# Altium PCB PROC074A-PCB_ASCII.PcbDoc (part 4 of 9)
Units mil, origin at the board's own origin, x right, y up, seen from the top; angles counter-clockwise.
Board outline 2755.91 x 5300 mil, 10 copper layers (Top Layer, L2-GND, L3-SIG1, L4-GND, L5-PWR/SIG, L6-SIG2, L7-PWR2, L8-SIG3, L9-GND, Bottom Layer), stack 67.57 mil thick; 586 components, 490 nets, 2137 pads, 1150 vias.
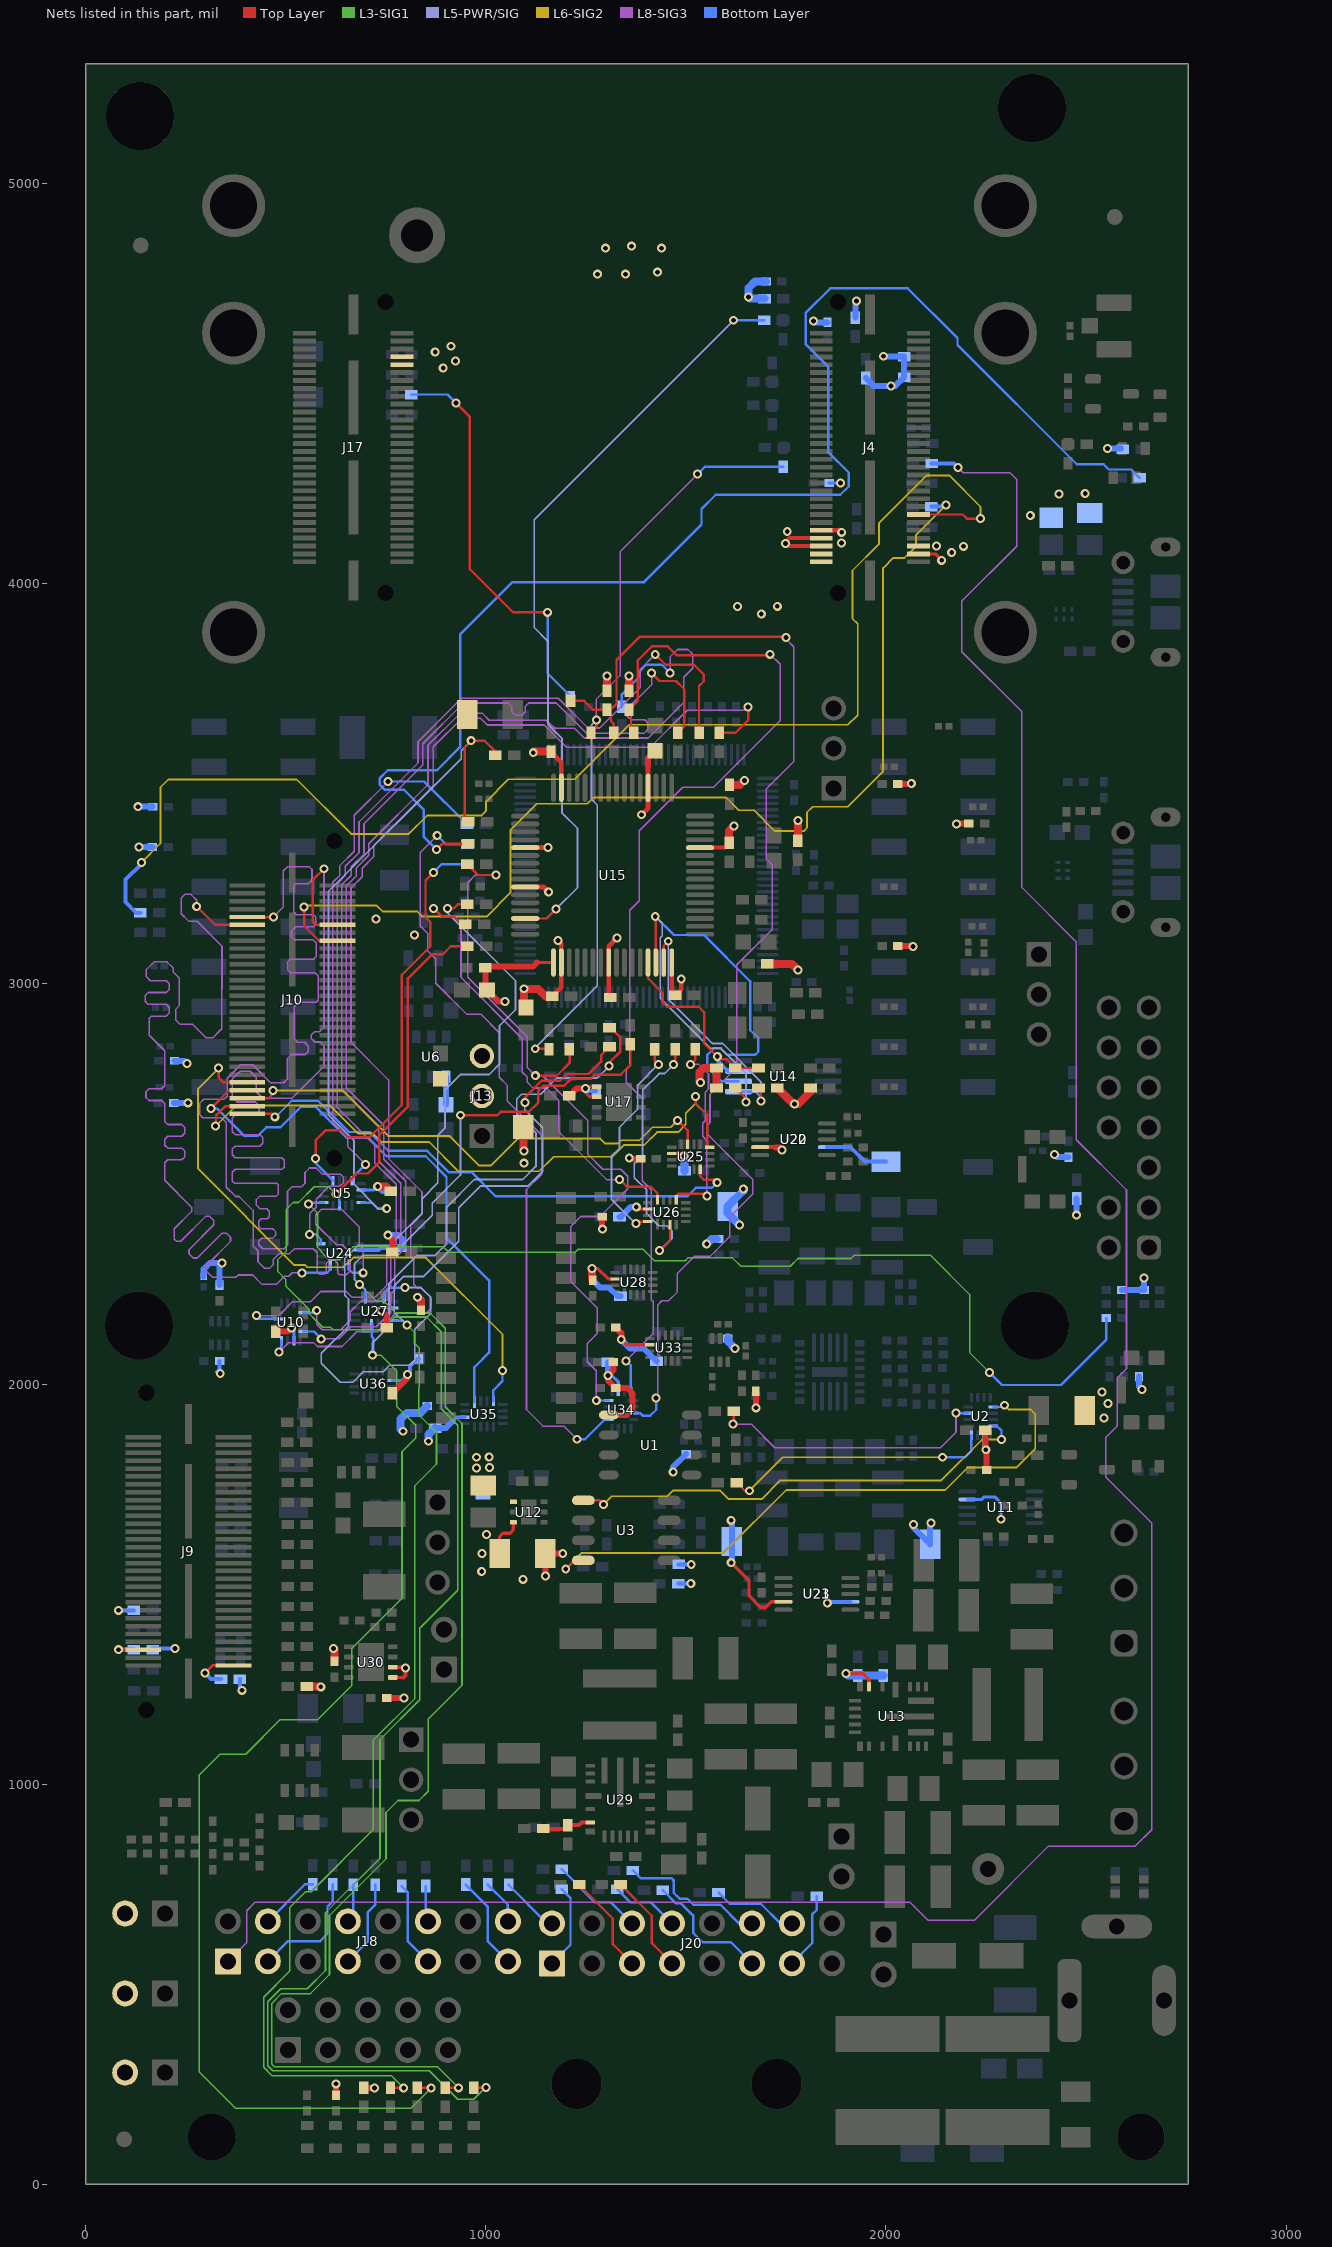
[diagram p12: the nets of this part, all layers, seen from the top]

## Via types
v1: diameter 22.4, hole 12.2, Top Layer to Bottom Layer, tented both sides, 1123 vias
v2: diameter 15.75, hole 7.87, Top Layer to Bottom Layer, tented both sides, 14 vias
v3: diameter 19.68, hole 7.87, Top Layer to Bottom Layer, tented both sides, 13 vias

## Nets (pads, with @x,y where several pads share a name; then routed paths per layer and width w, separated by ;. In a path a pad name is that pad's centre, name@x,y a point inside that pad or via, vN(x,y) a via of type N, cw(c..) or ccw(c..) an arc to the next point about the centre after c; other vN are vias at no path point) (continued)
60PIN_MISO1: J10.12 U24.8 | length 2879.4
  Top Layer w6: v1(595.37,3288.06) 567,3259.69 567,3156 575.41,3147.59 J10.12@629.09,3147.59
  L8-SIG3 w4: v1(559.37,2374.06) 559.37,2425.59 575.83,2442.05 575.83,2462.06 607.99,2494.22 635.22,2494.22 643,2502 643,2518 637,2524 592,2524 576,2540 559,2540 548,2529 548,2502 539.15,2493.15 515.31,2493.15 504.06,2481.9 504.06,2346.75 495.37,2338.06 442.31,2338.06 432.37,2348 432.37,2358.06 438.37,2364.06 466.37,2364.06 474.37,2372.06 474.37,2381.06 467.37,2388.06 437.37,2388.06 432.37,2393.06 432.37,2407.06 438.37,2413.06 453.46,2413.06 458.37,2417.97 458.37,2432.06 452.37,2438.06 435.37,2438.06 426.5,2446.92 426.5,2461.56 434,2469.06 475.37,2469.06 481.37,2475.06 481.37,2498.06 477.5,2501.93 371.5,2501.93 366.37,2507.06 366.37,2529.31 373.62,2536.56 490.56,2536.56 496,2542 496,2559.1 489.54,2565.56 373.62,2565.56 366.37,2572.81 366.37,2587.31 373.62,2594.56 434.92,2594.56 442.17,2601.81 442.17,2616.31 434.92,2623.56 373.62,2623.56 366.37,2630.81 366.37,2665 376.37,2675 425,2675 434,2684 434,2695 424,2705 378,2705 366.37,2716.63 366.37,2762.37 386.06,2782.06 410.96,2782.06 425.99,2767.03 425.99,2730.5 442.1,2714.39 515.56,2714.39 595.37,2794.21 595.37,2847 587.37,2855 572,2855 564,2863 564,2873 572,2881 585,2881 595.37,2891.37 v1(595.37,3288.06)
  Bottom Layer w6: v1(559.37,2374.06) 575.37,2374.06 587.39,2362.04 U24.8@587.39,2350.57
60PIN_MOSI1: J10.11 U24.4 | length 2967.3
  Top Layer w6: v1(277.22,3193.93) 323.55,3147.59 J10.11@403.5,3147.59
  L8-SIG3 w4: v1(277.22,3193.93) 277.22,3209.58 263,3223.8 247.4,3223.8 238.6,3215 238.6,3175.5 256.82,3157.28 277.22,3157.28 340.5,3094 340.5,2986.34 339.79,2985.63 339.79,2887.86 317.12,2865.2 301.22,2865.2 293,2873.41 ; 292.82,2873.24 267.12,2898.94 235.73,2898.94 224.33,2910.34 224.33,2936.44 233.95,2946.06 233.95,3014.48 218.98,3029.45 218.98,3039.06 202.84,3055.2 170.51,3055.2 151.57,3036.26 151.57,3018.12 161.39,3008.31 200.99,3008.31 208.37,3000.93 208.37,2986.18 200.99,2978.81 155.62,2978.81 148.25,2971.43 148.25,2956.68 155.62,2949.31 200.99,2949.31 208.37,2941.93 208.37,2927.18 200.99,2919.81 164.12,2919.81 158.37,2914.06 158.37,2872.01 197.37,2833.01 197.37,2745.68 189.99,2738.31 157.95,2738.31 150.58,2730.93 150.58,2716.18 157.95,2708.81 189.99,2708.81 197.37,2701.43 197.37,2656.18 204.74,2648.81 239.99,2648.81 247.37,2641.43 247.37,2626.68 239.99,2619.31 204.74,2619.31 197.37,2611.93 197.37,2597.18 204.74,2589.81 239.99,2589.81 247.37,2582.43 247.37,2567.68 239.99,2560.31 204.74,2560.31 197.37,2552.93 197.37,2509.06 264.37,2442.06 264.37,2431.06 221.37,2388.06 221.37,2362.06 226.58,2356.84 237.01,2356.84 299.19,2419.01 309.62,2419.01 320.05,2408.58 320.05,2398.15 257.87,2335.98 257.87,2325.55 268.3,2315.12 278.73,2315.12 340.91,2377.29 351.34,2377.29 361.76,2366.86 361.76,2356.43 299.59,2294.26 299.59,2283.83 316.82,2266.61 375.11,2266.61 381.01,2272.51 417,2272.51 440.45,2249.06 476.06,2249.06 496.61,2269.61 507.43,2269.61 515.82,2278 v1(540,2278)
  Bottom Layer w6: v1(540,2278) 603.4,2278 611.01,2285.61 U24.4@611.01,2295.45
60PIN_NRST: J10.59 U25.4 | length 1373.4
  Top Layer w6: J10.59@403.5,2675.15 465.27,2675.15 v1(472.37,2668.06) ; U25.4@1535.68,2536.88 1535.68,2519.75 1544.43,2511 1571.21,2511 v1(1578.26,2503.95)
  Bottom Layer w6: v1@473.44,2666.8 514.57,2707.92 580.13,2707.92 658.06,2630 709.2,2630 755.95,2583.25 853.11,2583.25 906.73,2529.63 963.85,2529.63 1024.48,2469 1503.4,2469 1524.66,2490.26 1564.57,2490.26 v1(1578.26,2503.95)
60PIN_PGOOD_3V3: J4.14 R224.2 | length 3351.6
  Top Layer w6: J4.14@2081.5,4173.45 2191.98,4173.45 2202.37,4163.06 v1(2236.37,4163.06)
  L6-SIG2 w4.5: v1(139.37,3304.06) 186.48,3351.17 186.48,3491.17 206.37,3511.06 526.94,3511.06 663,3375 807,3375 852.86,3420.86 988.74,3420.86 1000.57,3432.69 1000.57,3455.79 1056.33,3511.56 1221.87,3511.56 1358.11,3647.8 1904.99,3647.8 1929.37,3672.18 1929.37,3900.11 1916.43,3913.06 1916.43,4033.47 1982.37,4099.41 1982.37,4151.52 2102.08,4271.23 2157.97,4271.23 2236.37,4192.83 v1(2236.37,4163.06)
  Bottom Layer w10: R224.2@136.38,3178 126,3178 99.63,3204.37 99.63,3260.71 139.37,3300.45 v1(139.37,3304.06)
60PIN_RS232RX: J10.55 U25.11 | length 1293.7
  Top Layer w6: J10.55@403.5,2714.52 456.9,2714.52 467.5,2725.12 v1(467.5,2734.06) ; v1(1479.37,2659.06) 1504.18,2634.24 U25.11@1504.18,2599.87
  L6-SIG2 w4.5: v1(467.5,2734.06) 641.94,2734.06 755.69,2620.31 908.69,2620.31 983,2546 1012,2546 1079.51,2613.51 1285.49,2613.51 1298,2601 1330,2601 1338.26,2609.26 1383.97,2609.26 1416.57,2641.86 1462.17,2641.86 v1(1479.37,2659.06)
60PIN_RS232TX: J10.57 U25.8 | length 1649.1
  Top Layer w6: v1(324.37,2645.06) 325.37,2646.06 325.37,2671.06 349.15,2694.84 J10.57@403.5,2694.84 ; v1(1524.37,2719.06) 1524.37,2701.06 1553.17,2672.26 1553.17,2598.13 U25.8@1559.3,2592
  L6-SIG2 w4.5: v1(324.37,2645.06) 375.31,2696 611,2696 681,2626 719,2626 740,2605 858.06,2605 931.26,2531.8 1132.8,2531.8 1169.18,2568.18 1315.96,2568.18 1345.03,2597.26 1395.26,2597.26 1427.86,2629.86 1480.37,2629.86 1499.37,2648.86 1499.37,2650.49 1499.57,2650.69 1499.57,2677.26 1524.37,2702.06 v1(1524.37,2719.06)
60PIN_SCL: J10.53 U35.1 | length 1451.6
  Top Layer w6: v1(312.92,2688.79) 358.34,2734.21 J10.53@403.5,2734.21
  Bottom Layer w6: v1(312.92,2688.79) 328.21,2688.79 397,2620 429.74,2620 451.49,2641.74 486.26,2641.74 537.37,2692.86 575,2692.86 652.02,2615.84 705.16,2615.84 751.57,2569.43 849.76,2569.43 901.57,2517.63 901.57,2365.43 1008,2259 1008,2078.62 971.38,2042 U35.1@971.38,1954.53
60PIN_SDA: J10.51 U35.4 | length 1502.6
  Top Layer w6: v1(331.99,2789.59) 331.99,2766.22 344.32,2753.89 J10.51@403.5,2753.89
  L6-SIG2 w4.5: v1(331.99,2789.59) 280.72,2738.32 280.72,2538.21 521.48,2297.45 548.06,2297.45 553.7,2291.81 643.99,2291.81 668.24,2316.06 850.21,2316.06 1041.62,2124.65 v1(1041.62,2033.5)
  Bottom Layer w6: U35.4@1018.62,1956.5 1018.62,1984.5 1041.62,2007.5 v1(1041.62,2033.5)
60PIN_SPICLK1: J10.9 U24.1 | length 2892.6
  Top Layer w6: J10.9@403.5,3167.28 v1(468.72,3167.28)
  L8-SIG3 w4: v1(468.72,3167.28) 493.57,3192.13 493.57,3282.86 503.23,3292.52 559.12,3292.52 565.34,3286.3 565.34,3259.4 556.7,3250.76 524.26,3250.76 519.78,3246.28 519.78,3179.1 526.07,3172.81 569.36,3172.81 574.38,3167.79 574.38,3148.65 569.05,3143.32 525.01,3143.32 514.14,3132.45 514.14,3118.3 522.06,3110.38 568.07,3110.38 575.57,3102.88 575.57,3068.21 569.22,3061.86 511.17,3061.86 504.37,3055.06 504.37,3036.06 512.17,3028.26 572.74,3028.26 581.2,3019.8 581.2,2959.47 575.79,2954.06 531.37,2954.06 521.37,2944.06 521.37,2862.63 530,2854 547.17,2854 556.17,2845 556.17,2831.12 548.75,2823.7 513.9,2823.7 504.06,2813.86 504.06,2762.3 495.01,2753.26 461.73,2753.26 417.07,2797.92 387.23,2797.92 353.37,2764.06 353.37,2719.36 345.57,2711.56 294.67,2711.56 284.37,2701.26 284.37,2674.06 292.57,2665.86 339.14,2665.86 351.37,2653.63 351.37,2492.06 374.74,2468.69 383.17,2468.69 418.09,2433.77 418.09,2345.31 430.37,2333.03 430.37,2305.86 447.23,2289 459.17,2289 468.17,2298 468.17,2310.86 483.37,2326.06 509.22,2326.06 521.43,2338.27 568.37,2338.27 578.57,2328.07 578.57,2279.86 583.37,2275.06 596.37,2275.06 601.37,2280.06 601.37,2302.06 609.37,2310.06 621.37,2310.06 629.37,2302.06 629.37,2278.06 634.37,2273.06 651.22,2273.06 661.37,2283.21 661.37,2327.63 641,2348 626.39,2348 575,2399.39 575,2422.83 589.12,2436.96 638.85,2436.96 683.15,2392.66 683.15,2348.33 693.37,2338.11 v1(693.37,2278.06)
  Bottom Layer w6: U24.1@658.25,2297.42 658.25,2286.8 667,2278.06 v1(693.37,2278.06)
60PIN_VREF_JTAG: J9.1 R242.1 | length 126
  Top Layer w6: v1(297.62,1277.53) 316.71,1296.62 J9.1@369.17,1296.62
  Bottom Layer w10: v1(297.62,1277.53) 312.62,1262.53 R242.1@338,1262.53
BOOST_3V3_IN: C75.1 L7.2 R256.2 U12.4 U12.6 | length 103.3
  Top Layer w7.8: R256.2@1034.28,1576.06 1034.28,1618.93 1042.41,1627.06 1060.6,1627.06 1068.6,1635.06 ; 1068.6,1644.06 U12.6@1068.6,1654.47
  Top Layer w8: 1068.6,1635.06 1068.6,1644.06
  other v1: 989.62,1531.53 990.15,1576.06 1001.46,1623.69 976.37,1790.06 1009.37,1791.06 976.37,1817.06 1008.37,1817.37
BP_LP_3V3: J13.3 R122.2
  other v1: 822,3122.12 725,3162
BRD_3V3: C2.2 C4.1 C27.1 C28.1 C71.1 C72.1 C73.1 C88.2 C92.1 C93.1 C94.1 C95.1 C114.1 C115.1 C116.1 C117.1 J4.4 J4.6 J13.2 J17.7 J17.9 P4.2 P5.2 P6.2 R4.1 R9.2 R13.2 R15.2 R18.2 R19.2 R22.2 R23.2 R24.2 R25.2 R26.2 R34.2 R37.2 R51.2 R55.2 R56.2 R57.2 R58.2 R60.2 R61.2 R64.2 R71.2 R73.2 R106.1 R119.2 R120.2 R123.2 R147.1 R151.2 R176.1 R177.1 R178.2 R179.2 R180.2 R203.2 R209.2 R241.2 R242.2 R243.2 R245.1 R247.2 R249.2 R250.2 R255.2 R256.1 R260.2 R274.2 R275.2 R289.2 R291.2 R395.1 U1.5 U2.14 U5.14 U6.1 U10.14 U11.9 U20.9 U24.14 U25.14 U26.14 U27.14 U28.14 U30.1 U30.2 U33.14 U34.14 U35.14 U36.14 | length 4269.6
  Top Layer w6: v1@586.73,1243.95 v1(587.35,1243.32) ; v1@1290.68,2387.74 v1(1291.37,2387.06) ; v1@2066.43,3095 v1(2067.37,3094.06)
  Top Layer w7.8: U30.1@767.53,1266.61 794.28,1266.61 ; U30.2@767.53,1292.2 797.22,1292.2 v1(799.37,1290.06) ; 1351.31,2098.12 U33.14@1409.35,2098.12
  Top Layer w8: v1(1264.85,2288.67) 1279.88,2288.67 1305.68,2262.87 U28.14@1322.76,2262.87 ; v1(1338.37,2111.06) 1351.31,2098.12 ; v1(1375.99,2442.88) 1381.44,2437.43 U26.14@1405,2437.43 ; U25.14@1464.81,2576.25 1488.53,2576.25 v1@1495.05,2569.73 ; J4.4@2081.5,4074.95 2123.48,4074.95 v1(2139.37,4059.06)
  Top Layer w9.8: U20.9@1685.43,2592.01 1724.37,2592.01
  Top Layer w10: 794.28,1266.61 799.37,1271.7 v1(799.37,1290.06)
  Top Layer w15: C72.1@474.37,2131.06 505.28,2131.06 v1(513.82,2139.6) ; R123.2@625.37,222.59 v1(625.37,251) ; R255.2@694.26,240.62 v1(721.74,240.62) ; v1(738.37,2184.06) 751.99,2170.43 C94.1@751.99,2141.06 ; C88.2@752.1,1215 v1(795.31,1215) ; v1(755.37,2372.06) 766.38,2361.05 C27.1@766.38,2330 ; C117.1@765.61,1977.43 804.37,2016.19 v1(804.37,2024.06) ; v1(1148.62,1520.06) 1148.46,1520.22 R256.1@1148.46,1576.06 v1(1192.15,1576.06) ; v1@1290.68,2387.74 R209.2@1290.68,2418.06 ; U1.5@1307.59,1922.63 1353.04,1922.63 1367.05,1936.64 1367.05,1975.82 1352.87,1990 C2.2@1324.69,1990 1304.99,2009.69 v1(1304.99,2021.43) 1318.41,2034.86 R19.2@1318.41,2055 ; R18.2@1324.69,2141.06 1338.37,2127.37 v1(1338.37,2111.06) ; v1(1358.37,2565.06) 1360.29,2563.13 R151.2@1386.66,2563.13 ; R180.2@1674.58,1982.51 1674.58,1941.04 v1(1674.96,1940.66) ; 1724.37,2590.69 1734.73,2590.69 v1(1740.37,2585.06) ; R61.2@2029.69,3095 v1@2066.43,3095 ; R60.2@2029.69,3500 2062.31,3500 v1(2063.37,3501.06) ; v1(2176.37,3400.06) 2177.31,3401 R64.2@2207.31,3401 ; C4.1@2248.62,1885 2248.62,1836.7 v1(2249.52,1835.8) 2251.43,1833.89 R260.2@2251.43,1785.05
  Top Layer w20: R243.2@551.88,1243.95 v1@586.73,1243.95 ; v1(619.37,1339.06) 621.37,1337.06 R395.1@621.37,1306.74 ; v1(729.63,2494) 750.01,2494 C73.1@762.01,2482 ; v1(829.37,2217) 837.37,2209 R25.2@837.37,2184.06 ; v1(1264.85,2288.67) 1264.85,2261.84 R24.2@1267,2259.69
  Bottom Layer w6: v1@1886.28,4252.35 v1(1886.63,4252)
  Bottom Layer w7.8: U5.14@688.87,2484.87 720.5,2484.87 v1(729.63,2494) ; R249.2@1858.19,4252.35 v1@1886.28,4252.35
  Bottom Layer w8: v1(513.82,2139.6) 520.24,2133.18 U10.14@520.24,2107.81 ; v1(738.37,2184.06) 744.24,2189.93 U27.14@769.61,2189.93 ; U36.14@765.61,2008.93 789.24,2008.93 v1(804.37,2024.06) ; 915,1905 927.13,1917.13 U35.14@947.76,1917.13 ; v1(1304.99,2021.43) 1315.07,2021.43 1330.87,2005.63 U34.14@1330.87,1982.54 ; U11.9@2203.71,1711.74 2239.53,1711.74 2245.68,1717.89 2272.11,1717.89 2287.37,1702.63 v1(2287.37,1662.06) ; U2.14@2245.03,1871.87 2245.03,1840.29 v1(2249.52,1835.8)
  Bottom Layer w10: v1(81.62,1434.53) 81.74,1434.42 R245.1@119.95,1434.42 ; R241.2@167.2,1335.99 167.2,1338.51 222.6,1338.51 v1(222.89,1338.8) ; v1@328.37,2030.06 334.37,2036.06 R176.1@334.37,2057.58 ; R242.2@385.25,1262.53 385.25,1239.91 v1(390.62,1234.53) ; U24.14@681.87,2334.82 731.43,2334.82 736.61,2340 R203.2@790.31,2340 ; v1(804.37,2024.06) 810.37,2030.06 810.37,2044.66 828.5,2062.8 R37.2@832.96,2062.8 ; C71.1@1480.88,1501.13 v1(1512.22,1501.13) ; R15.2@1481.79,1549.28 v1(1513.37,1549.28)
  Bottom Layer w15: v1(130.37,3443.06) 130.43,3443 R55.2@167.31,3443 ; v1(133.43,3342) R56.2@166.63,3342 ; R58.2@220.06,2702.06 254.37,2702.06 v1(255.37,2703.06) ; R57.2@221.74,2808.06 246.37,2808.06 v1(253.37,2801.06) ; R178.2@294.37,2269.06 294.37,2287 310.37,2303 v1(340,2303) 334.43,2297.43 R179.2@334.43,2247.48 ; v1(729.63,2494) 741.63,2482 R26.2@764.94,2482 ; v1(755.37,2372.06) 781.53,2372.06 790.31,2363.28 R203.2@790.31,2340 ; C116.1@873.37,1890.06 900.06,1890.06 915,1905 ; C28.1@900.37,2698.29 900.78,2698.7 U6.1@900.78,2767.86 ; v1(1264.85,2288.67) 1264.85,2261.79 1285.52,2241.12 1307.84,2241.12 1328.96,2220 C95.1@1336.38,2220 ; v1(1304.99,2021.43) C115.1@1304.99,2054.06 ; C93.1@1333.99,2418.06 1337.72,2418.06 1362.54,2442.88 v1(1375.99,2442.88) ; v1(1338.37,2111.06) 1360,2089.43 1393.95,2089.43 C114.1@1426.38,2057 ; v1(1468.25,1780.06) 1468.25,1792.93 R4.1@1500.32,1825 ; v1(1819.37,4657.06) 1822.75,4653.68 R247.2@1854.01,4653.68 ; R9.2@1923.63,4665.62 1923.63,4704.32 v1(1926.37,4707.06) ; R13.2@1949.63,4514.76 1969.39,4495 v1(2012.63,4495) 2023.39,4495 R22.2@2045.38,4516.99 R274.2@2045.38,4567.99 2044.38,4569 v1(1993.63,4569) ; v1@2422.37,2573.06 2428.11,2567.31 R119.2@2456,2567.31 ; v1(2476.37,2422.06) R34.2@2476.37,2463.81 ; R71.2@2589.69,2235 R51.2@2645.31,2235 v1(2645.31,2265) ; R120.2@2632.37,2018.37 2632.37,1994.06 v1(2640.37,1986.06)
  Bottom Layer w20: v1(792.37,1882.06) 786.57,1887.86 786.57,1912.37 802.25,1928.06 836.47,1928.06 R23.2@853.42,1945 ; v1(829.37,2217) 837.37,2209 R250.2@837.37,2184.06 ; v1(856.37,1857.06) 856.37,1871.53 856.87,1872.03 856.87,1873.56 C116.1@873.37,1890.06 ; v1(1495.26,2569.95) 1496.42,2568.79 C92.1@1496.42,2533.13 ; v1(1552,2350) 1564.46,2362.46 R106.1@1576.45,2362.46 ; R177.1@1604.76,2113.82 1604.76,2106.86 v1(1622.42,2089.2) ; v1(1634.04,2397.39) 1604.18,2427.25 R289.2@1604.18,2443.8 1643.37,2482.99 v1(1643.37,2487.06) ; R275.2@1696.38,4712.99 1660.43,4712.99 v1(1656.37,4717.06) 1656.37,4738.63 1656,4739 1673.06,4756.06 R73.2@1700.68,4756.06
  other v1: 1093,1512 2545,1915 2554.73,1951.79 2540,1980 336,2026 2421.31,2574.11 2164.37,4078.06 2193.37,4094.06 2126.63,4095 893.37,4540.06 924.37,4557.06 873.37,4580.06 912.37,4594.06
CAN1_RX: R8.1 U2.3 | length 709.6
  Top Layer w6: v1(1617.49,1900) 1619.62,1902.13 R8.1@1619.62,1931.85
  L8-SIG3 w4: v1(1617.49,1900) 1663,1900 1721.94,1841.06 2136.39,1841.06 2175.02,1879.69 v1(2175.02,1927.66)
  Bottom Layer w6: v1(2175.02,1927.66) 2175.69,1926.99 U2.3@2205.66,1926.99
CAN1_TX: R6.1 U2.16 | length 695.1
  Top Layer w6: R6.1@1634.31,1753.85 R6.1@1626.62,1753.85 1647.14,1733.33 v1(1658.63,1733.33)
  L6-SIG2 w4.5: v1(1658.63,1733.33) 1742.36,1817.06 v1(2141.37,1817.06)
  Bottom Layer w6: v1(2141.37,1817.06) 2197.37,1817.06 2213.53,1833.22 U2.16@2213.53,1871.87 2213.02,1871.35 U2.16@2213.02,1860.14
CAN2_RX: U2.9 U3.4 | length 1553
  Top Layer w6: v1(1199.62,1537.53) 1221.37,1559.28 U3.4@1243.6,1559.28
  L6-SIG2 w4.5: v1(1199.62,1537.53) 1240.15,1578.06 1593.37,1578.06 1750.57,1735.26 2148.08,1735.26 2203.93,1791.11 2326.11,1791.11 2373,1838 2373,1925 2361.4,1936.6 2306.4,1936.6 v1(2296,1947)
  Bottom Layer w6: U2.9@2268.65,1942.74 2291.74,1942.74 v1(2296,1947)
CAN2_TX: U2.12 U3.1 | length 1181.5
  Top Layer w6: U3.1@1243.6,1709.28 1284.37,1709.28 v1(1294.37,1699.28)
  L6-SIG2 w4.5: v1(1294.37,1699.28) 1314.57,1719.48 1453.17,1719.48 1467.35,1733.65 1585.56,1733.65 1606.82,1712.39 1689.18,1712.39 1736.05,1759.26 2138.14,1759.26 2240.17,1861.29 v1(2288.86,1861.29)
  Bottom Layer w6: U2.12@2268.65,1895.49 2276.93,1895.49 2288.86,1883.57 v1(2288.86,1861.29)
CB_PMIC_1V0: J4.1 J4.3 R288.2 U23.9 | length 312
  Top Layer w8: v1(1613.22,1553.46) 1658.01,1508.66 1658.01,1470.41 1686.15,1442.28 1699.77,1442.28 1713.27,1455.78 U23.9@1743.74,1455.78
  Bottom Layer w15: v1(1613.22,1553.46) 1615,1555.24 R288.2@1615,1606.1 1615,1657.68 v1(1613.22,1659.46)
  other v1: 1688.37,3925.06 1629.37,3943.06 1728.37,3944.06
CB_PMIC_1V2: J4.5 J4.7 R287.2 U22.9 | length 347.8
  Top Layer w10: v1@1748.14,4102.67 1756.16,4094.65 J4.5@1838.5,4094.65 ; v1@1750.25,4105.95 1758.64,4114.35 J4.7@1838.5,4114.35
  Bottom Layer w10: U22.9@1852.76,2592.01 1911.53,2592.01 ; 1911.53,2591.88 1947.38,2556.03 R287.2@2000.26,2556.03
  other v1: 1749.34,4100.61 1753.27,4131.33
CB_PMIC_1V8: J4.9 R286.2 U21.9 | length 232.8
  Top Layer w12: J4.9@1838.5,4134.05 1884.38,4134.05 v1(1889.37,4129.06)
  Bottom Layer w10: v1(1853.37,1453.06) 1856.1,1455.78 U21.9@1911.06,1455.78
  Bottom Layer w15: v1(2068.43,1649.34) 2068.43,1641.33 R286.2@2110.31,1599.46 2110.31,1650.55 v1(2112.22,1652.46)
  other v1: 1889.02,4102.63
DCA_SYNC_IN: J10.16 R346.2 | length 2724.3
  Top Layer w6: v1(545.85,3192.59) 545.85,3144.86 582.49,3108.22 J10.16@629.09,3108.22
  L6-SIG2 w4.5: v1(545.85,3192.59) 549.26,3196 727.06,3196 742,3181.06 828.8,3181.06 841.36,3168.5 1001.81,3168.5 1061.2,3227.89 1061.2,3384.31 1127.45,3450.56 1253.9,3450.56 1269.4,3466.06 1600.34,3466.06 1632.34,3434.06 1670.34,3434.06 1722.2,3382.2 1794.23,3382.2 1802.68,3390.65 1802.68,3429.03 1816.71,3443.06 1904.37,3443.06 1992.83,3531.52 1992.83,4039.52 2018.37,4065.06 2046.37,4065.06 2075.37,4094.06 2075.37,4122.74 v1(2149.63,4197)
  Bottom Layer w10: R346.2@2113.63,4193.05 2145.68,4193.05 v1(2149.63,4197)
DMM_MUX_IN: J18.1 R281.2 | length 6430.3
  L8-SIG3 w4: J18.1@355,557 402,604 402,683.62 423.17,704.79 2060.21,704.79 2105,660 2221.37,660 2406.43,845.06 2623.28,845.06 2664.37,886.15 2664.37,1652.63 2549,1768 2549,1866 2578,1895 2578,2015 2601.2,2038.2 2601.2,2484.92 2475.49,2610.63 2475.49,3105.19 2339.79,3240.89 2339.79,3680.45 2189.62,3830.62 2189.62,3957.06 2326.97,4094.41 2326.97,4260.83 2309.8,4278 2193.43,4278 v1(2180.37,4291.06)
  Bottom Layer w10: R281.2@2114.25,4301 2170.43,4301 v1(2180.37,4291.06)
DMM_TRACE_CLK: J18.4 R36.1 | length 150.3
  Bottom Layer w6: J18.4@455,657 547.38,749.38 R36.1@567,749.38
DMM_TRACE_CTL: J18.3 R35.2 | length 306.6
  Bottom Layer w6: J18.3@455,557 505.63,607.63 586,607.63 604.2,625.83 604.2,694 617,706.8 R35.2@617,749.38
DMM_TRACE_D0: J18.7 R38.2 | length 219.3
  Bottom Layer w6: J18.7@655,557 704.37,606.37 704.37,679.06 723.19,697.87 R38.2@723.19,748.03
DMM_TRACE_D1: J18.8 R39.1 | length 120.3
  Bottom Layer w6: J18.8@638.19,673.81 J18.8@655,657 668.19,670.19 R39.1@668.19,748.03
DMM_TRACE_D2: J18.11 R40.2 | length 215.6
  Bottom Layer w6: R40.2@789.37,745.43 804.37,730.43 804.37,607.63 J18.11@855,557
DMM_TRACE_D3: J18.12 R42.1 | length 90.8
  Bottom Layer w6: R42.1@849.37,745.43 849.37,662.63 J18.12@855,657
DMM_TRACE_D4: J18.15 R45.2 | length 235.8
  Bottom Layer w6: R45.2@949.37,749.06 1004.37,694.06 1004.37,607.63 J18.15@1055,557
DMM_TRACE_D5: J18.16 R46.1 | length 113
  Bottom Layer w6: R46.1@1004.37,749.06 1055,698.43 J18.16@1055,657
DMM_TRACE_D6: J20.1 R52.2 | length 206
  Bottom Layer w6: J20.1@1170,557 1211.52,598.52 1211.52,715.32 R52.2@1189.99,736.85
DMM_TRACE_D7: J20.2 R53.1 | length 147.6
  Bottom Layer w6: R53.1@1057.15,748.03 1153.18,652 J20.2@1165,652
DMM_TRACE_D8: J20.5 R233.2 | length 256.7
  Top Layer w6: R233.2@1232.99,749.06 1232.99,748.01 1317,664 1317,600 J20.5@1365,552
  Top Layer w10: J20.5@1365,552 J20.5@1365,557
DMM_TRACE_D9: J20.6 R234.1 | length 230.9
  Bottom Layer w6: R234.1@1189.99,787.06 1273.05,704 1313,704 J20.6@1365,652
DMM_TRACE_D10: J20.7 R273.2 | length 250.2
  Top Layer w6: R273.2@1336.61,749.06 1414.5,671.17 1414.5,602.5 J20.7@1465,552
DMM_TRACE_D11: J20.8 R294.1 | length 171.5
  Bottom Layer w6: R294.1@1328.61,736.85 1361.41,704.06 1412.94,704.06 J20.8@1465,652
DMM_TRACE_D12: J20.11 R295.2 | length 323.4
  Bottom Layer w6: R295.2@1442.58,734.82 1475.61,701.79 1488,701.79 1518,671.79 1518,628.68 1541.68,605 1612,605 J20.11@1665,552
DMM_TRACE_D13: J20.12 R296.1 | length 370.4
  Bottom Layer w6: R296.1@1367.41,784.06 1386.41,765.06 1463.54,765.06 1469.37,759.23 1469.37,728.3 1483.88,713.79 1503.18,713.79 1518.49,698.48 1586.17,698.48 1632.65,652 J20.12@1665,652
DMM_TRACE_D14: J20.13 R297.2 | length 193.5
  Bottom Layer w6: J20.13@1765,552 1815.37,602.37 1815.37,674 1827.11,685.74 R297.2@1827.11,719.8
DMM_TRACE_D15: J20.14 R298.1 | length 215.4
  Bottom Layer w6: R298.1@1581.47,729.06 1609.52,701 1687,701 1736,652 J20.14@1765,652
EECLK: R185.1 U14.2 U15.62 | length 1496.3
  Top Layer w6: v1(1423.37,3169.06) 1424.96,3167.47 U15.62@1424.96,3053.45 ; R185.1@1623.62,2740 1650.53,2713.09 v1(1650.53,2704.9)
  L5-PWR/SIG w4.5: v1(1423.37,3169.06) 1441,3151.43 1441,3120.5 1435.67,3115.17 1435.67,2964.84 1539.8,2860.71 ; 1539.8,2860.66 1558.66,2841.8 ; 1558.71,2841.8 1561.25,2839.26 1586.74,2839.26 1650.53,2775.46 v1(1650.53,2704.9)
  Bottom Layer w6: v1(1423.37,3169.06) 1470.03,3122.4 1545.17,3122.4 1661,3006.56 1661,2884.42 1680.7,2864.72 1680.7,2830.6 1672.96,2822.86 1603.14,2822.86 1586.74,2839.26 1570,2839.26 1553.8,2823.05 1553.8,2791.68 1588.86,2756.62 U14.2@1631.44,2756.62
EECS: R186.1 U14.1 U15.63 | length 676.3
  Top Layer w6: U15.63@1444.64,3053.45 1444.64,3095.57 v1(1455.87,3106.8) ; R186.1@1681.38,2740 1687.57,2733.81 v1(1687.57,2707.06)
  L5-PWR/SIG w4.5: v1(1455.87,3106.8) 1455.87,2961.61 1551.8,2865.68 ; 1551.8,2865.63 1563.63,2853.8 ; 1563.68,2853.8 1566.22,2851.26 1591.71,2851.26 1687.57,2755.39 v1(1687.57,2707.06)
  Bottom Layer w6: U14.1@1631.44,2731.03 1674.02,2731.03 1687.57,2717.48 v1(1687.57,2707.06)
EEDATA: R187.1 R193.1 U14.3 U15.61 | length 542.6
  Top Layer w6: U15.61@1405.37,3053.55 U15.61@1405.27,3053.45 1405.27,3014.15 1441.9,2977.53 1441.9,2953.3 1452.14,2943.06 1531.94,2943.06 1545.57,2929.42 1545.57,2851.86 v1(1578.37,2819.06) 1585.77,2811.65 1601.97,2811.65 R187.1@1623.62,2790 R193.1@1681.38,2790
  Bottom Layer w10: v1(1578.37,2819.06) 1578.37,2808.4 1604.56,2782.21 U14.3@1631.44,2782.21
EMU_RSTN: J9.6 R241.1 | length 99.9
  Top Layer w6: v1(81.8,1335.99) J9.6@143.57,1335.99
  Bottom Layer w10: v1(81.8,1335.99) R241.1@119.95,1335.99
FPWM1: R403.1 R404.2 U13.16 | length 175.9
  Top Layer w10: v1(1900.37,1276.06) 1942.84,1276.06 1957.99,1260.91 U13.16@1957.99,1243.86
  Bottom Layer w20: v1(1900.37,1276.06) 1904.99,1271.43 R404.2@1929.37,1271.43 R403.1@1993.37,1271.43
FPWM2: R315.1 R318.2 U29.16 | length 135.6
  Top Layer w10: R315.1@1142.99,889.06 1144.37,887.68 1204.37,887.68 R318.2@1214.37,897.68 ; R318.2@1204.37,897.68 R318.2@1214.37,897.68 ; U29.16@1261.12,904.25 1239,904.25 1232.42,897.68 R318.2@1214.37,897.68
FTDI_3V3: C66.1 C67.1 C68.1 C69.1 C70.1 L5.1 L6.1 R181.2 R185.2 R186.2 R187.2 R189.2 R190.2 R204.1 R221.2 U15.20 U15.31 U15.42 U15.50 U15.56 | length 1379.4
  Top Layer w6: v1@1093.62,2583.8 v1(1095.37,2582.06) ; v1(1302.78,3770.22) v1@1303,3770.44 ; v1(1357.78,3770.22) v1@1358,3770.44 ; R204.1@1608,3498.62 R204.1@1609,3498.62
  Top Layer w11.8: U15.42@1098.19,3242.43 1144.57,3242.43 v1@1150.66,3236.34 ; C67.1@1162.78,3580.56 1188.74,3554.6 U15.31@1188.74,3490.46 ; C70.1@1165.54,2969.18 1188.74,2992.38 U15.50@1188.74,3053.45 1188.74,3100.26 v1(1180,3109) ; C68.1@1310.75,2966.18 1306.85,2970.08 U15.56@1306.85,3053.45 1306.85,3094.53 v1(1327.37,3115.06) ; v1(1389,3423) 1405.27,3439.27 U15.20@1405.27,3490.46 1405.27,3545.06
  Top Layer w15: v1@1150.66,3236.34 v1(1157,3230) ; 1405.27,3545.06 1405.27,3565.18 C66.1@1422.78,3582.68
  Top Layer w20: v1@1093.62,2583.8 R221.2@1093.62,2642.53 ; C69.1@1100,2941.5 1095.37,2946.13 v1(1095.37,2988.06) 1130.37,2988.06 1149.24,2969.18 C70.1@1165.54,2969.18 ; v1(1118.37,3578.06) 1120.87,3580.56 C67.1@1162.78,3580.56 ; R190.2@1302.78,3732.8 v1(1302.78,3770.22) ; R189.2@1357.78,3732.8 v1(1357.78,3770.22) ; v1(1536.37,2754.06) 1534.37,2756.06 1534.37,2780.06 1544.31,2790 R187.2@1576.38,2790 R185.2@1576.38,2740 ; R204.1@1609,3497.62 1634.62,3497.62 v1(1646,3509) ; L5.1@1703.62,3050 1765,3050 v1(1780,3035) ; R186.2@1728.62,2740 1768.57,2700.06 v1(1771.37,2700.06) 1780.92,2700.06 1811.38,2730.51 R181.2@1811.38,2740 ; L6.1@1779.85,3358.21 v1(1779.85,3408.85)
  other v1: 1095,2552
FTDI_60PIN_40PIN_NRST: R124.1 U5.5 | length 2520.6
  L3-SIG1 w4: v1(556.63,2450) 579.09,2427.54 579.09,2342.3 588.57,2332.82 588.57,2330.1 608.44,2310.23 634.52,2310.23 667.65,2343.37 893.01,2343.37 907.05,2329.33 1222.65,2329.33 1230.58,2337.26 1392.52,2337.26 1421.65,2308.13 1498,2308.13 1505.16,2315.29 1616.71,2315.29 1637.42,2294.58 1760.78,2294.58 1780.05,2313.86 1912.8,2313.86 1920.87,2321.92 2111.08,2321.92 2209,2224 2209,2079 v1(2259,2029)
  Bottom Layer w6: v1(556.63,2450) 560.01,2453.38 U5.5@594.39,2453.38 ; v1(2259,2029) 2290.37,1997.63 2437.48,1997.63 2550.31,2110.47 R124.1@2550.31,2165
FTDI_CLK1: R182.2 U10.16 | length 3069.2
  Top Layer w6: R182.2@1582.78,3627.8 1623.8,3627.8 1655.37,3659.37 v1(1655.37,3692.06)
  L8-SIG3 w4: v1(483.37,2080.06) 506.07,2102.75 570.11,2102.75 579,2093.86 640.36,2093.86 677.56,2131.06 729.56,2131.06 776.16,2177.66 851.03,2177.66 863.82,2190.45 863.82,2215.02 838.7,2240.14 829,2240.14 820,2249.14 820,2311 812.34,2318.66 812.34,2396.84 840.25,2424.75 840.25,2480.18 756.82,2563.61 756.82,2760.04 662.8,2854.06 662.8,3240 690.7,3267.9 690.7,3289.3 719.37,3317.97 719.37,3345.52 868.57,3494.72 868.57,3592.73 940.09,3664.26 986.65,3664.26 1003.65,3647.26 1145.62,3647.26 1200.82,3592.06 1411.37,3592.06 1503.37,3684.06 1647.37,3684.06 v1(1655.37,3692.06)
  Bottom Layer w6: v1(483.37,2080.06) 488.75,2085.43 U10.16@488.75,2107.81
FTDI_CS1: R188.2 U10.12 | length 3003.7
  L8-SIG3 w4: v1(588.37,2113.06) 632.26,2113.06 662.26,2143.06 725.94,2143.06 761.93,2179.04 761.93,2225.24 772.57,2235.88 772.57,2314.75 799.46,2341.64 799.46,2506.73 744.57,2561.62 744.57,2646.63 650.8,2740.4 650.8,3245 676.42,3270.62 676.42,3290.58 707.37,3321.52 707.37,3350.49 855.37,3498.49 855.37,3596.51 935.12,3676.26 991.62,3676.26 1008.62,3659.26 1150.59,3659.26 1170.59,3639.26 1221.74,3639.26 1246.19,3614.81 1406.12,3614.81 1494.69,3703.37 1494.69,3766.69 1517,3789 1517,3824 1505,3836 1479,3836 1460.37,3817.37 v1(1460.37,3777.59)
  Bottom Layer w6: U10.12@543.87,2131.43 569.99,2131.43 v1(588.37,2113.06) ; R188.2@1339.85,3693.21 1339.85,3723.72 1384,3767.87 1384,3781 1401,3798 1439.96,3798 v1(1460.37,3777.59)
FTDI_DSS_LOGGER: R192.2 R210.2 R361.2 | length 1910.9
  Top Layer w6: v1(1123.37,2838.06) 1156.29,2838.06 R210.2@1157.78,2836.56 ; R192.2@1262.78,3627.8 1276.37,3641.39 v1(1276.37,3660.06)
  L5-PWR/SIG w4.5: v1(1123.37,2838.06) 1123.37,2840.2 1278.37,2995.2 1278.37,3207.46 1278.57,3207.66 1278.57,3447.26 1264.17,3461.66 1264.17,3647.86 v1(1276.37,3660.06)
  L8-SIG3 w4: v1(1276.37,3660.06) 1276.37,3712.06 1335.37,3771.06 1335.37,4080.56 v1(1529.37,4274.56)
  Bottom Layer w6: v1(1529.37,4274.56) 1547.56,4292.76 R361.2@1743.25,4292.76
FTDI_GPIO_0: R215.2 U26.16 | length 545.5
  Top Layer w6: v1(1375,2401) 1379.93,2405.93 U26.16@1405,2405.93 ; R215.2@1421.93,2836.56 1422.4,2836.09 1422.4,2808.02 v1(1431.37,2799.06)
  L5-PWR/SIG w4.5: v1(1375,2401) 1313.89,2462.11 1313.89,2569.89 1334,2590 1334,2641.88 1379.67,2687.55 1379.67,2747.36 v1(1431.37,2799.06)
FTDI_GPIO_1: R216.2 U26.3 | length 691.9
  Top Layer w6: v1(1434.37,2334.06) 1435.94,2334.06 1460.12,2358.24 U26.3@1460.12,2398.06 ; v1(1469.37,2799.06) 1472.93,2802.62 R216.2@1472.93,2836.56
  L5-PWR/SIG w4.5: v1(1434.37,2334.06) 1434.88,2334.06 1465.4,2364.58 1465.4,2382.11 1451.68,2395.84 1432.22,2395.84 1401.74,2426.31 1401.74,2485.26 1371,2516 1371,2550.18 1392.17,2571.35 1392.17,2735.36 1432.86,2776.06 1446.37,2776.06 v1(1469.37,2799.06)
FTDI_GPIO_2: R217.2 U26.9 | length 502.6
  Top Layer w6: U26.9@1475.87,2461.05 1475.87,2470.78 1480.94,2475.86 1546.57,2475.86 v1(1552.37,2470.06) ; v1(1511.93,2798.93) 1523.37,2810.37 R217.2@1523.37,2836.43
  L8-SIG3 w4: v1(1511.93,2798.93) 1532.49,2798.93 1556.57,2774.86 1556.57,2737.23 1548.17,2728.83 1548.17,2658.17 1542.17,2652.17 1542.17,2619.72 1552.37,2609.52 v1(1552.37,2470.06)
FTDI_HOST_INTR1: R198.2 R199.2 U5.16 | length 1753.7
  Top Layer w6: R199.2@956.38,3405 947.17,3414.21 947.17,3591.86 v1(963.37,3608.06) 996.94,3608.06 1023.75,3581.25 R198.2@1023.75,3572.06
  L5-PWR/SIG w4.5: v1(752.16,2438.52) 731.37,2438.52 670.71,2499.18 670.71,2608.29 606.37,2672.63 606.37,3231.09 938.37,3563.09 938.37,3583.06 v1(963.37,3608.06)
  Bottom Layer w6: U5.16@688.87,2453.38 714.81,2453.38 729.67,2438.52 v1(752.16,2438.52)
FTDI_I2C_SCL: R189.1 R194.2 U34.16 | length 2664.4
  Top Layer w6: R194.2@1362.78,3627.8 1362.78,3680.56 R189.1@1357.78,3685.56 1379.57,3707.35 1379.57,3808.67 1415,3844.11 1454.32,3844.11 1476.37,3822.06 1708.37,3822.06 v1(1710.37,3824.06)
  L8-SIG3 w4: v1(1350.37,2058.06) 1418.43,2126.12 1418.43,2206.05 1413.57,2210.91 1413.57,2485.43 1391.17,2507.83 1391.17,2714.26 1351.17,2754.26 1351.17,2787.29 1359.37,2795.49 1359.37,3184.06 1383.37,3208.06 1383.37,3383.06 1492.37,3492.06 1568.79,3492.06 1735.57,3658.84 1735.57,3798.86 v1(1710.37,3824.06)
  Bottom Layer w6: v1(1350.37,2058.06) 1362.37,2046.06 U34.16@1362.37,1982.54
FTDI_I2C_SDA: R190.1 R195.2 R196.2 U34.3 | length 3045.5
  Top Layer w6: R196.2@1212.37,3707.68 1245.75,3707.68 1267.87,3685.56 R190.1@1302.78,3685.56 ; R195.2@1319.78,3627.8 1319.78,3650.06 1312.78,3657.06 1312.78,3675.56 R190.1@1302.78,3685.56 ; v1(1750.37,3866.06) 1748.37,3868.06 1491.37,3868.06 1491.32,3868.11 1384.85,3868.11 1326.37,3809.62 1326.37,3700.06 1311.87,3685.56 R190.1@1302.78,3685.56
  L8-SIG3 w4: v1(1425.66,1965.26) 1429.37,1968.97 1429.37,2197.73 1439.6,2207.96 1456.67,2207.96 1478.78,2230.07 1478.78,2277.15 1520.62,2318.99 1560.09,2318.99 1609.14,2368.05 1609.14,2416.63 1666.64,2474.13 1666.64,2512.22 1554.17,2624.69 1554.17,2647.2 1560.17,2653.2 1560.17,2723.86 1627.37,2791.06 1627.37,3047.78 1716,3136.41 1716,3298.28 1700.8,3313.48 1700.8,3487.52 1769.57,3556.29 1769.57,3843 1750.37,3862.2 v1(1750.37,3866.06)
  Bottom Layer w6: U34.3@1370.24,1927.43 1385.37,1927.43 ; 1391.79,1921 1385.37,1927.43 ; v1(1425.66,1965.26) 1425.66,1935.71 1410.95,1921 1392.42,1921 1385.99,1927.43 1385.37,1927.43
FTDI_MISO1: R184.2 U10.9 | length 2935.3
  Top Layer w6: v1(1414.26,3776.93) 1433.93,3757.26 1475.28,3757.26 1495.69,3736.85 1495.69,3643.9 R184.2@1479.59,3627.8
  L8-SIG3 w4: v1(577.17,2184.29) 577.17,2149.26 590.82,2135.61 637.49,2135.61 661.15,2159.27 661.15,2180.84 686.62,2206.31 726.61,2206.31 762.57,2242.27 762.57,2321.72 787.46,2346.61 787.46,2501.76 732.57,2556.65 732.57,2641.1 639.37,2734.3 639.37,3247.71 663.64,3271.99 663.64,3293.36 695.37,3325.08 695.37,3400.52 842.37,3547.52 842.37,3600.48 944.15,3702.26 1055.87,3702.26 1064.37,3693.76 1064.37,3679.75 1072.87,3671.25 1089.87,3671.25 1098.37,3679.75 1098.37,3693.76 1106.87,3702.26 1175.71,3702.26 1250.91,3627.06 1396.26,3627.06 1404.7,3635.5 1404.7,3652.26 1396.76,3660.2 1362.6,3660.2 1353.4,3669.4 1353.4,3687.65 1414.26,3748.51 v1(1414.26,3776.93)
  Bottom Layer w6: U10.9@543.87,2178.68 571.56,2178.68 v1(577.17,2184.29)
FTDI_MOSI1: R183.2 U10.3 | length 3003.5
  Top Layer w6: v1(1423.37,3823.91) 1449.48,3797.79 1520.2,3797.79 1544.57,3773.42 1544.57,3756.69 1532.78,3744.9 R183.2@1532.78,3627.8
  L8-SIG3 w4: v1(427,2171) 482.31,2171 517.37,2206.06 562.22,2206.06 587.42,2231.26 651.17,2231.26 665.57,2216.86 722.71,2216.86 752.57,2246.72 752.57,2327.78 775.74,2350.95 775.74,2499.28 722.32,2552.7 722.32,2597.04 628.37,2690.99 628.37,3250.85 648.73,3271.22 648.73,3294 682.82,3328.08 682.82,3404.93 830.37,3552.49 830.37,3605.45 939.18,3714.26 1180.68,3714.26 1255.08,3639.86 1284.74,3639.86 1385.37,3740.49 1385.37,3785.91 v1(1423.37,3823.91)
  Bottom Layer w6: v1(427,2171) 435.07,2162.93 U10.3@480.87,2162.93
FTDI_NERR_OUT: R207.2 U26.12 | length 1152.5
  Top Layer w6: v1(869.37,3189.06) 889.93,3168.5 921.1,3168.5 940.45,3149.15 R207.2@953.23,3149.15 ; v1(1334.37,2511.06) 1352.37,2493.06 1412.37,2493.06 1428.62,2476.8 U26.12@1428.62,2461.05
  L8-SIG3 w4: v1(869.37,3189.06) 891.17,3167.26 923.02,3167.26 937.8,3152.47 937.8,3016.73 1091.17,2863.37 1091.17,2779.64 1103.17,2767.64 1103.17,2754.83 1118,2740 1150.96,2740 1182.57,2708.39 1182.57,2629.86 1301.37,2511.06 v1(1334.37,2511.06)
FTDI_NERRIN: R206.2 U27.12 | length 2154.8
  Top Layer w6: v1(903.86,3188.7) 919.7,3188.7 930.15,3199.15 R206.2@953.23,3199.15
  L5-PWR/SIG w4.5: v1(798,2241) 837.84,2241 861.78,2217.06 861.78,2176.29 822.17,2136.68 822.17,2059.29 809.74,2046.86 759.17,2046.86 742.95,2030.64 693.92,2030.64 667.84,2004.56 635.76,2004.56 588.52,2051.8 588.52,2076.82 656.57,2144.87 656.57,2212.61 647.37,2221.81 647.37,2313.8 679.57,2346 759.11,2346 840.72,2427.61 840.72,2463.58 879.83,2502.69 879.83,2621.53 897.54,2639.25 897.54,2734.6 936.43,2773.49 1007.72,2773.49 1034.36,2800.13 1034.36,2896.22 1074,2935.86 1074,3007.62 903.86,3177.76 v1(903.86,3188.7)
  Bottom Layer w6: U27.12@745.99,2213.55 745.99,2229.88 757.11,2241 v1(798,2241)
FTDI_NRST: R208.2 R253.1 U5.3 | length 4387.8
  Top Layer w6: v1(625.37,2475.02) 676.55,2526.2 705.08,2526.2 733.88,2555 733.88,2622.68 805,2693.8 805,3013.85 865.21,3074.06 892.06,3074.06 912.15,3094.15 R208.2@953.23,3094.15 ; R253.1@969.5,240.62 998.62,240.62 v1(1000,242)
  L3-SIG1 w4: 575,2159.27 592.02,2142.26 611.5,2142.26 617.9,2135.86 740.17,2135.86 771.97,2167.66 851.34,2167.66 888.56,2130.44 888.56,1938.22 929.72,1897.06 929.72,1484.44 834.57,1389.29 834.57,1210.93 735.37,1111.73 735.37,815.03 599.2,678.86 599.2,533.89 553.79,488.48 487.09,488.48 454.52,455.91 454.52,296.21 467.24,283.48 858.52,283.48 930,212 970,212 v1(1000,242) ; 575,2159.31 557.97,2176.34 557.97,2186.88 499.8,2245.05 499.8,2261.47 480.17,2281.1 480.17,2311.15 501.37,2332.35 501.37,2437.06 518.06,2453.75 531.63,2453.75 570.94,2493.06 607.33,2493.06 v1(625.37,2475.02)
  Bottom Layer w6: v1(625.37,2475.02) 633.76,2466.63 U5.3@633.76,2445.5
FTDI_PMIC_EN: R197.2 R356.2 | length 1025.5
  Top Layer w6: v1(925.37,4452.06) 960,4417.43 960,4036.75 1067.69,3929.06 v1(1154.37,3929.06)
  Bottom Layer w6: R356.2@813.62,4473.35 904.08,4473.35 v1(925.37,4452.06) ; v1(1154.37,3929.06) 1154.37,3776.63 1210.49,3720.51 R197.2@1210.49,3716.01
FTDI_PMIC_OUT_SOR0: R10.1 R212.2 U27.16 | length 3643.1
  Top Layer w6: R10.1@761.37,240.62 v1(794.62,240.62) v1@795,241 ; v1(1097.37,2704.06) 1097.37,2716.05 1139.38,2758.06 1185.81,2758.06 1202.61,2774.86 1256.74,2774.86 1287.88,2806 1287.88,2821.94 R212.2@1308.99,2843.06
  L3-SIG1 w4: v1(794.62,240.62) 764.04,271.2 465.38,271.2 444.52,292.06 444.52,467.12 509.37,531.97 509.37,691.06 549.37,731.06 563.43,731.06 718.82,886.45 718.82,1110.13 822.57,1213.88 822.57,1746.26 876.57,1800.26 876.57,1878.86 832.67,1922.76 832.67,1992.22 832.96,1992.51 832.96,2090.47 821.57,2101.86 821.57,2129.08 v1(803,2147.65)
  L5-PWR/SIG w4.5: v1(803,2147.65) 770.74,2179.91 770.74,2245.99 793.44,2268.7 843.93,2268.7 932,2356.77 932,2440.77 985.91,2494.68 1104.4,2494.68 1142,2532.28 1142,2641 1097.37,2685.63 v1(1097.37,2704.06)
  Bottom Layer w6: U27.16@769.61,2158.43 792.22,2158.43 v1(803,2147.65)
FTDI_RS232RX: R202.2 U5.12 | length 1344.5
  L8-SIG3 w4: v1(699.37,2549.06) 654.24,2594.19 654.24,2617.92 617.37,2654.79 617.37,3254 635.18,3271.8 635.18,3296 670.82,3331.64 670.82,3421.5 v1(755.37,3506.06)
  Bottom Layer w6: U5.12@665.25,2508.5 665.25,2514.94 v1(699.37,2549.06) ; v1(755.37,3506.06) 845.75,3506.06 R202.2@952.75,3399.06
FTDI_RS232TX: R205.2 U5.9 | length 1101.5
  Top Layer w6: v1(574.37,2564.06) 574.37,2609.39 599.04,2634.06 637.15,2634.06 654.21,2617 709.31,2617 789.57,2697.26 789.57,3022.57 861,3094 861,3155 849.17,3166.83 849.17,3258.86 v1(869.37,3279.06)
  Bottom Layer w6: v1(574.37,2564.06) 574.37,2552.13 U5.9@618.01,2508.5 ; v1(869.37,3279.06) 889.47,3299.15 R205.2@953.23,3299.15
FTDI_SUSPEND_N: R191.2 R218.2 | length 3556
  Top Layer w6: v1(876.37,3336.06) 890.31,3350 R218.2@956.38,3350
  Bottom Layer w6: v1(876.37,3336.06) 845.17,3367.26 845.17,3435.26 794.57,3485.86 747,3485.86 735.17,3497.69 735.17,3514.42 754.8,3534.06 877.85,3534.06 935.7,3591.9 935.7,3873.7 1066.5,4004.5 1395.44,4004.5 1539,4148.06 1539,4187 1574.75,4222.75 1885.95,4222.75 1906.83,4243.63 1906.83,4278.06 1855.43,4329.46 1855.43,4543.57 1799.2,4599.8 1799.2,4648.66 ; 1799.17,4649.4 1799.17,4677 1860.8,4738.63 2054.59,4738.63 2178.8,4614.43 2178.8,4597.09 2476.89,4299 2544.06,4299 2557,4286.06 2612.99,4286.06 R191.2@2633.99,4265.06
FTDI_SYNC_OUT_SOR1: R213.2 R251.1 U27.3 | length 4231.5
  Top Layer w6: R251.1@829,240.62 v1(863.38,240.62) ; v1(1308.08,2794.85) 1308.08,2803.27 1336.1,2831.29 1336.1,2866.33 1311.37,2891.06 R213.2@1308.99,2891.06
  L3-SIG1 w4: v1(716.37,2072.06) 737.74,2072.06 777.37,2032.43 777.37,1944.06 824.57,1896.86 824.57,1865.06 790.37,1830.86 790.37,1464.52 664.91,1339.06 664.91,1246.76 579.46,1161.31 486.14,1161.31 399.84,1075 335.31,1075 284,1023.69 284,280.02 374.02,190 812.76,190 v1(863.38,240.62)
  L5-PWR/SIG w4.5: v1(716.37,2072.06) 716.37,2102.34 758.12,2144.09 758.12,2251.56 828,2321.44 872.78,2321.44 901.76,2350.42 901.76,2442.23 970.74,2511.21 1092.21,2511.21 1125,2544 1125,2628 1077.17,2675.83 1077.17,2712.42 1089,2724.26 1137,2724.26 1177.66,2764.91 1278.14,2764.91 v1(1308.08,2794.85)
  Bottom Layer w6: U27.3@714.5,2150.56 714.5,2118.5 718.95,2114.05 718.95,2074.63 v1(716.37,2072.06)
FTDI_TDO_SOR2: R214.2 R252.1 U27.9 | length 4080
  Top Layer w6: R252.1@898,240.62 930.99,240.62 v1(931.37,241) ; v1(936.57,2671.86) 1028.77,2671.86 1037.97,2681.06 1108.6,2681.06 1130.17,2702.63 1130.17,2703.42 1131,2704.25 1131,2732.71 1144.35,2746.06 1195.9,2746.06 1212.7,2762.86 1261.75,2762.86 1272.19,2773.3 1337.18,2773.3 1361.57,2797.69 1361.57,2847.23 R214.2@1359.37,2849.43
  L3-SIG1 w4: v1(684.37,2249.06) 726.37,2207.06 745.59,2207.06 774.99,2177.66 860.41,2177.66 898.56,2139.51 898.56,1943.41 940.34,1901.63 940.34,1246.83 856.08,1162.57 856.08,982.3 832.84,959.06 780.37,959.06 750.37,929.06 750.37,813.06 609.2,671.89 609.2,523.89 561.79,476.48 489.23,476.48 464.52,451.77 464.52,300.35 471.38,293.48 878.89,293.48 v1(931.37,241)
  L5-PWR/SIG w4.5: v1(684.37,2249.06) 671.37,2262.06 671.37,2300.02 693.35,2322 765.51,2322 865.92,2422.41 865.92,2452.1 936.57,2522.75 v1(936.57,2671.86)
  Bottom Layer w6: v1(684.37,2249.06) 698.75,2234.68 U27.9@698.75,2213.55
FTDI_UART3_TX: R43.2 U34.9 | length 1955.9
  L8-SIG3 w4: v1(878.37,3371.06) 836.37,3329.06 836.37,3144.59 854.65,3126.31 854.65,3082.7 875,3062.35 875,3001.51 951.76,2924.76 987.16,2924.76 1033.66,2878.25 1033.66,2766.68 1053,2747.34 1053,2708.26 1139.57,2621.69 1139.57,2524.46 1101.44,2486.32 1101.44,1936.35 1142.79,1895 1194.94,1895 v1(1227.94,1862)
  Bottom Layer w6: v1(878.37,3371.06) 900.37,3349.06 R43.2@953.75,3349.06 ; v1(1227.94,1862) 1247.4,1862 1297.08,1911.68 U34.9@1307.25,1911.68
FTDI_UART4_TX: R200.2 R211.2 U34.12 | length 1958.1
  Top Layer w6: R200.2@953.23,3299.15 980.08,3272.3 v1(1025.5,3272.3) ; v1(1123.46,2770.7) 1177.27,2770.7 1209.37,2802.8 1209.37,2835.12 R211.2@1207.93,2836.56
  L8-SIG3 w4: v1(1025.5,3272.3) 973.61,3272.3 954.37,3253.06 954.37,3017.14 1103.17,2868.34 1103.17,2790.99 v1(1123.46,2770.7) 1123.6,2770.56 1142.44,2770.56 1255.01,2657.98 1255.01,2574.38 1292.34,2537.06 1336.94,2537.06 1354.57,2519.42 1354.57,2488.26 1285.17,2418.86 1237.26,2418.86 1212.27,2393.87 1212.27,2256.1 1278,2190.37 1278,2126 1253.53,2101.53 1253.53,2055.47 1276,2033 v1(1276,1958.92)
  Bottom Layer w6: v1(1276,1958.92) U34.12@1307.25,1958.92
FTDI_VBUS: C62.1 R219.2 R220.2 R228.2 R254.2 U17.1 U17.2 | length 184.8
  Top Layer w8: U17.2@1277.24,2717.8 1260.12,2717.8 1249.37,2728.54 v1(1249.37,2739.06) 1253.7,2743.39 U17.1@1277.24,2743.39
  Top Layer w15: C62.1@1207.99,2720.06 1226.99,2739.06 v1(1249.37,2739.06)
  Bottom Layer w10: v1(1249.37,2739.06) 1255.86,2732.57 R228.2@1275.51,2732.57
  Bottom Layer w15: v1(2553.47,4338.43) R254.2@2587.69,4338.43
  other v1: 2360.8,4171 2433,4225 2498.02,4226.06 1279.37,4774.06 1349.37,4774.06 1429.37,4779.06 1299.37,4839.06 1439.37,4839.06 1364.37,4844.06
FTDI_VCORE: C56.1 C57.1 C58.1 C59.1 U15.12 U15.37 U15.49 U15.64 | length 602.8
  Top Layer w6: v1@1154.85,3340.85 v1(1155,3341)
  Top Layer w8: 1127.76,3053.45 U15.49@1169.05,3053.45
  Top Layer w10: U15.12@1535.19,3340.85 1595.83,3340.85 C56.1@1607.78,3352.8
  Top Layer w11.8: U15.37@1098.19,3340.85 v1@1154.85,3340.85 ; U15.64@1464.33,3053.45 1464.33,2980.69 C57.1@1473.07,2971.95 1488.37,2987.26 v1(1488.37,3012.06)
  Top Layer w15: v1(1048,2956.6) 1031.39,2956.6 C58.1@1002.99,2985 998.62,2989.37 C59.1@998.62,3040 1002.38,3043.76 1118.07,3043.76 1127.76,3053.45
  Top Layer w20: C56.1@1607.78,3352.8 1607.78,3382.78 v1(1620,3395)
FTDI_WARMRST: R357.2 U15.46 | length 1908.1
  Top Layer w6: U15.46@1098.19,3163.69 1151.69,3163.69 v1(1175,3187)
  L5-PWR/SIG w4.5: v1(1175,3187) 1229,3241 1229,3389 1190,3428 1190,3614 1155,3649 1155,3857 1121,3891 1121,4160.69 v1(1619.37,4659.06)
  Bottom Layer w6: v1(1619.37,4659.06) 1619.43,4658.99 R357.2@1695.38,4658.99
